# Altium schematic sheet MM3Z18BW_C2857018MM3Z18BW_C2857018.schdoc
size 127 x 101 mm
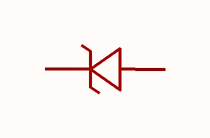
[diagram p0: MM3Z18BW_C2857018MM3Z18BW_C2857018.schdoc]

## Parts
D?  mm3z18bw_c2857018  [SOD-323_L1.7-W1.3-LS2.6-RD]  (value not drawn)

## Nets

Not connected (* = marked no-connect by the designer): D? 1(C) 2(A)

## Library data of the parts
D? = mm3z18bw_c2857018: 二极管配置:1个独立式;稳压值(标称值):18V;稳压值(范围值):17.64V~18.36V;耗散功率(Pd):400mW;; Manufacturer: JSMSEMI(杰盛微); AddInBom: yes; ModelId: 8f7582057468434a979d3a4d6e318d8a; ModelTransform: 100.394,49.2125,0,0,0,0,0,0,0; Diode Configuration: 1个独立式; Zener Voltage(Nom): 18V; Reverse Leakage Current (Ir): 100nA@13V; Pd - Power Dissipation: 400mW; Impedance(Zzt): 45Ω; Operating Junction Temperature Range: -55℃~+150℃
